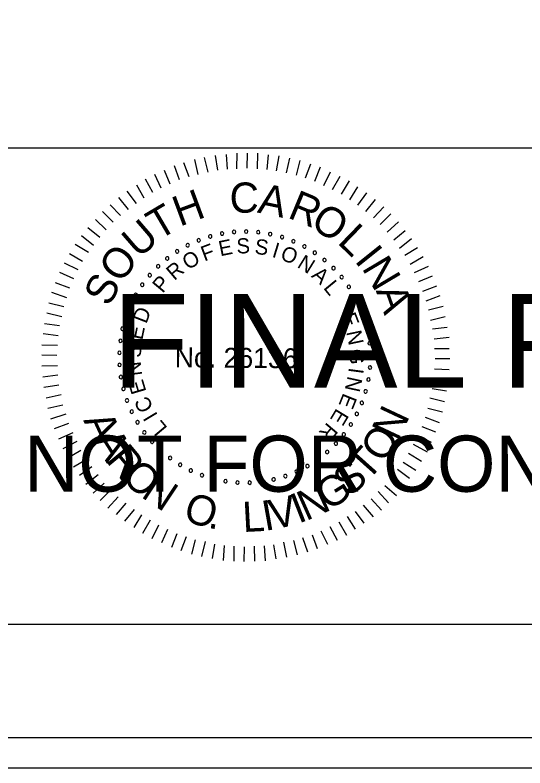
# Model space of a CAD drawing. Extents: x 967 to 1326, y 964 to 2304.
# Drawn here: x 1170.56 to 1189.3, y 1523.72 to 1551.36 of the extents above; entities that cross this region are included whole.
import ezdxf

# ---------------------------------------------------------------- set-up
doc = ezdxf.new("R2010")
doc.units = 0
for name, color, linetype in [('RD_PD_PaveShd', 7, 'Continuous'), ('RD_XS_Misc_Line', 7, 'Continuous'), ('RD_XS_PaveOvlay', 7, 'Continuous'), ('RD_XS_TX_Elev_EX', 7, 'Continuous'), ('RD_XS_TX_Elev_PR', 7, 'Continuous')]:
    doc.layers.add(name, color=color, linetype=linetype)

msp = doc.modelspace()

# ---------------------------------------------------------------- linework, layer by layer
at = {"layer": 'RD_PD_PaveShd'}
for p, q in [((996.114, 1546.486), (1323.886, 1546.486)), ((1323.886, 1528.983), (996.114, 1528.983))]:
    msp.add_line(p, q, dxfattribs=at)
at = {"layer": 'RD_XS_Misc_Line'}
for p, q in [((1178.01, 1545.663), (1177.93, 1546.209)), ((1178.364, 1545.699), (1178.33, 1546.244)), ((1178.717, 1545.719), (1178.722, 1546.295)), ((1179.093, 1545.739), (1179.098, 1546.292)), ((1179.469, 1545.713), (1179.489, 1546.288)), ((1179.829, 1545.687), (1179.872, 1546.231)), ((1180.174, 1545.646), (1180.271, 1546.19)), ((1176.964, 1545.419), (1176.769, 1545.935)), ((1177.287, 1545.508), (1177.169, 1546.054)), ((1177.657, 1545.597), (1177.53, 1546.128)), ((1180.535, 1545.573), (1180.662, 1546.102)), ((1180.902, 1545.478), (1181.045, 1546.022)), ((1181.231, 1545.384), (1181.428, 1545.896)), ((1176.264, 1545.156), (1176.053, 1545.657)), ((1176.61, 1545.306), (1176.423, 1545.83)), ((1181.584, 1545.265), (1181.78, 1545.786)), ((1175.933, 1545.005), (1175.699, 1545.506)), ((1181.905, 1545.109), (1182.154, 1545.606)), ((1182.226, 1544.953), (1182.506, 1545.45)), ((1175.308, 1544.634), (1175.036, 1545.12)), ((1175.624, 1544.846), (1175.352, 1545.332)), ((1182.562, 1544.789), (1182.85, 1545.27)), ((1175.03, 1544.445), (1174.681, 1544.9)), ((1182.86, 1544.572), (1183.163, 1545.053)), ((1183.158, 1544.378), (1183.484, 1544.828)), ((1174.729, 1544.217), (1174.372, 1544.665)), ((1183.447, 1544.145), (1183.811, 1544.587)), ((1174.435, 1543.997), (1174.062, 1544.399)), ((1183.729, 1543.92), (1184.116, 1544.316)), ((1174.172, 1543.753), (1173.776, 1544.148)), ((1183.98, 1543.672), (1184.368, 1544.061)), ((1173.909, 1543.479), (1173.52, 1543.858)), ((1184.232, 1543.394), (1184.657, 1543.767)), ((1173.684, 1543.197), (1173.242, 1543.546)), ((1184.475, 1543.108), (1184.892, 1543.45)), ((1173.451, 1542.9), (1173.009, 1543.256)), ((1184.687, 1542.807), (1185.128, 1543.156)), ((1173.257, 1542.64), (1172.776, 1542.936)), ((1173.039, 1542.312), (1172.559, 1542.6)), ((1184.885, 1542.544), (1185.355, 1542.832)), ((1185.081, 1542.213), (1185.56, 1542.493)), ((1172.883, 1542.006), (1172.379, 1542.256)), ((1185.24, 1541.904), (1185.756, 1542.145)), ((1172.727, 1541.677), (1172.215, 1541.904)), ((1185.399, 1541.573), (1185.907, 1541.791)), ((1172.571, 1541.333), (1172.051, 1541.53)), ((1185.549, 1541.226), (1186.057, 1541.414)), ((1172.461, 1540.974), (1171.91, 1541.178)), ((1185.669, 1540.865), (1186.185, 1541.06)), ((1172.351, 1540.652), (1171.807, 1540.787)), ((1185.759, 1540.541), (1186.297, 1540.667)), ((1172.286, 1540.276), (1171.727, 1540.419)), ((1185.832, 1540.165), (1186.371, 1540.298)), ((1172.191, 1539.955), (1171.647, 1540.029)), ((1185.906, 1539.842), (1186.436, 1539.906)), ((1172.15, 1539.587), (1171.598, 1539.653)), ((1185.964, 1539.473), (1186.51, 1539.53)), ((1172.124, 1539.234), (1171.548, 1539.239)), ((1185.977, 1539.12), (1186.514, 1539.115)), ((1172.105, 1538.866), (1171.545, 1538.871)), ((1185.997, 1538.751), (1186.542, 1538.747)), ((1172.118, 1538.482), (1171.542, 1538.471)), ((1185.971, 1538.368), (1186.508, 1538.348)), ((1172.138, 1538.136), (1171.585, 1538.072)), ((1185.952, 1538.022), (1186.497, 1537.949)), ((1172.173, 1537.768), (1171.627, 1537.688)), ((1185.888, 1537.655), (1186.417, 1537.566)), ((1172.262, 1537.414), (1171.701, 1537.296)), ((1185.808, 1537.302), (1186.345, 1537.175)), ((1172.321, 1537.037), (1171.774, 1536.911)), ((1185.729, 1536.926), (1186.265, 1536.792)), ((1172.425, 1536.707), (1171.871, 1536.519)), ((1185.634, 1536.597), (1186.146, 1536.401)), ((1172.53, 1536.36), (1172.007, 1536.173)), ((1185.508, 1536.253), (1186.013, 1536.057)), ((1172.681, 1536.029), (1172.165, 1535.788)), ((1172.831, 1535.705), (1172.323, 1535.441)), ((1185.352, 1535.924), (1185.857, 1535.675)), ((1185.188, 1535.603), (1185.7, 1535.33)), ((1172.982, 1535.374), (1172.497, 1535.094)), ((1185.024, 1535.274), (1185.498, 1534.987)), ((1173.194, 1535.042), (1172.709, 1534.762)), ((1184.822, 1534.946), (1185.288, 1534.658)), ((1173.384, 1534.78), (1172.936, 1534.453)), ((1184.62, 1534.687), (1185.055, 1534.353)), ((1173.612, 1534.478), (1173.164, 1534.129)), ((1184.403, 1534.389), (1184.814, 1534.033)), ((1173.832, 1534.177), (1173.437, 1533.812)), ((1184.155, 1534.092), (1184.574, 1533.72)), ((1174.091, 1533.945), (1173.689, 1533.541)), ((1183.899, 1533.864), (1184.28, 1533.454)), ((1174.35, 1533.674), (1173.97, 1533.263)), ((1183.644, 1533.597), (1184.024, 1533.18)), ((1174.64, 1533.442), (1174.275, 1533.022)), ((1174.937, 1533.209), (1174.58, 1532.782)), ((1183.358, 1533.37), (1183.715, 1532.944)), ((1175.212, 1533.014), (1174.932, 1532.549)), ((1182.764, 1532.952), (1183.059, 1532.482)), ((1183.065, 1533.141), (1183.384, 1532.709)), ((1175.525, 1532.812), (1175.245, 1532.331)), ((1175.83, 1532.633), (1175.588, 1532.136)), ((1182.463, 1532.755), (1182.743, 1532.269)), ((1176.159, 1532.477), (1175.94, 1531.98)), ((1181.8, 1532.431), (1182.041, 1531.93)), ((1182.124, 1532.581), (1182.396, 1532.08)), ((1176.503, 1532.321), (1176.307, 1531.816)), ((1176.855, 1532.211), (1176.651, 1531.69)), ((1177.177, 1532.1), (1177.05, 1531.572)), ((1181.122, 1532.175), (1181.31, 1531.652)), ((1181.476, 1532.28), (1181.664, 1531.771)), ((1177.545, 1532.036), (1177.409, 1531.484)), ((1177.897, 1531.933), (1177.808, 1531.412)), ((1178.25, 1531.892), (1178.207, 1531.34)), ((1178.603, 1531.866), (1178.598, 1531.313)), ((1178.978, 1531.84), (1178.974, 1531.295)), ((1179.355, 1531.86), (1179.365, 1531.307)), ((1179.715, 1531.88), (1179.749, 1531.327)), ((1180.061, 1531.915), (1180.149, 1531.393)), ((1180.423, 1532.012), (1180.541, 1531.458)), ((1180.791, 1532.07), (1180.926, 1531.54))]:
    msp.add_line(p, q, dxfattribs=at)
for centre, start, end in [((1178.609, 1543.397), 5.0653, 185.0653), ((1179.055, 1543.414), 359.5268, 179.5268), ((1179.055, 1543.414), 179.5268, 359.5268), ((1179.5, 1543.388), 353.9884, 173.9884), ((1177.312, 1543.091), 21.6807, 201.6807), ((1177.734, 1543.235), 16.1422, 196.1422), ((1177.734, 1543.235), 196.1422, 16.1422), ((1178.168, 1543.337), 10.6038, 190.6038), ((1178.168, 1543.337), 190.6038, 10.6038), ((1178.609, 1543.397), 185.0653, 5.0653), ((1179.5, 1543.388), 173.9884, 353.9884), ((1179.94, 1543.319), 168.4499, 348.4499), ((1179.94, 1543.319), 348.4499, 168.4499), ((1180.372, 1543.208), 162.9114, 342.9114), ((1180.372, 1543.208), 342.9114, 162.9114), ((1176.906, 1542.908), 27.2191, 207.2191), ((1176.906, 1542.908), 207.2191, 27.2191), ((1177.312, 1543.091), 201.6807, 21.6807), ((1180.79, 1543.056), 157.373, 337.373), ((1180.79, 1543.056), 337.373, 157.373), ((1181.193, 1542.864), 151.8345, 331.8345), ((1181.193, 1542.864), 331.8345, 151.8345), ((1176.52, 1542.686), 32.7576, 212.7576), ((1176.52, 1542.686), 212.7576, 32.7576), ((1181.574, 1542.634), 146.2961, 326.2961), ((1181.574, 1542.634), 326.2961, 146.2961), ((1176.156, 1542.428), 38.2961, 218.2961), ((1176.156, 1542.428), 218.2961, 38.2961), ((1181.932, 1542.368), 140.7576, 320.7576), ((1181.932, 1542.368), 320.7576, 140.7576), ((1175.82, 1542.135), 43.8345, 223.8345), ((1175.82, 1542.135), 223.8345, 43.8345), ((1182.263, 1542.069), 135.2191, 315.2191), ((1182.263, 1542.069), 315.2191, 135.2191), ((1175.513, 1541.812), 49.373, 229.373), ((1175.513, 1541.812), 229.373, 49.373), ((1182.563, 1541.74), 129.6807, 309.6807), ((1182.563, 1541.74), 309.6807, 129.6807), ((1175.239, 1541.461), 54.9114, 234.9114), ((1175.239, 1541.461), 234.9114, 54.9114), ((1182.83, 1541.383), 124.1422, 304.1422), ((1182.83, 1541.383), 304.1422, 124.1422), ((1175, 1541.085), 60.4499, 240.4499), ((1175, 1541.085), 240.4499, 60.4499), ((1183.061, 1541.002), 118.6038, 298.6038), ((1183.061, 1541.002), 298.6038, 118.6038), ((1174.798, 1540.687), 65.9884, 245.9884), ((1174.798, 1540.687), 245.9884, 65.9884), ((1183.255, 1540.601), 113.0653, 293.0653), ((1183.255, 1540.601), 293.0653, 113.0653), ((1174.636, 1540.272), 71.5268, 251.5268), ((1174.636, 1540.272), 251.5268, 71.5268), ((1183.408, 1540.182), 107.5268, 287.5268), ((1183.408, 1540.182), 287.5268, 107.5268), ((1174.514, 1539.843), 77.0653, 257.0653), ((1174.514, 1539.843), 257.0653, 77.0653), ((1183.521, 1539.751), 101.9884, 281.9884), ((1183.521, 1539.751), 281.9884, 101.9884), ((1174.435, 1539.405), 82.6038, 262.6038), ((1174.435, 1539.405), 262.6038, 82.6038), ((1183.592, 1539.311), 96.4499, 276.4499), ((1183.592, 1539.311), 276.4499, 96.4499), ((1174.398, 1538.961), 88.1422, 268.1422), ((1174.398, 1538.961), 268.1422, 88.1422), ((1183.619, 1538.866), 90.9114, 270.9114), ((1183.619, 1538.866), 270.9114, 90.9114), ((1174.404, 1538.515), 93.6807, 273.6807), ((1174.404, 1538.515), 273.6807, 93.6807), ((1183.604, 1538.421), 85.373, 265.373), ((1183.604, 1538.421), 265.373, 85.373), ((1174.453, 1538.072), 99.2191, 279.2191), ((1174.453, 1538.072), 279.2191, 99.2191), ((1183.546, 1537.979), 79.8345, 259.8345), ((1183.546, 1537.979), 259.8345, 79.8345), ((1174.545, 1537.636), 104.7576, 284.7576), ((1174.545, 1537.636), 284.7576, 104.7576), ((1183.445, 1537.545), 74.2961, 254.2961), ((1183.445, 1537.545), 254.2961, 74.2961), ((1174.678, 1537.211), 110.2961, 290.2961), ((1174.678, 1537.211), 290.2961, 110.2961), ((1183.303, 1537.122), 68.7576, 248.7576), ((1183.303, 1537.122), 248.7576, 68.7576), ((1174.852, 1536.8), 115.8345, 295.8345), ((1174.852, 1536.8), 295.8345, 115.8345), ((1183.121, 1536.716), 63.2191, 243.2191), ((1183.121, 1536.716), 243.2191, 63.2191), ((1175.065, 1536.409), 121.373, 301.373), ((1175.065, 1536.409), 301.373, 121.373), ((1182.9, 1536.328), 57.6807, 237.6807), ((1182.9, 1536.328), 237.6807, 57.6807), ((1175.314, 1536.039), 126.9114, 306.9114), ((1175.314, 1536.039), 306.9114, 126.9114), ((1182.643, 1535.964), 52.1422, 232.1422), ((1182.643, 1535.964), 232.1422, 52.1422), ((1175.598, 1535.696), 132.4499, 312.4499), ((1175.598, 1535.696), 312.4499, 132.4499), ((1182.353, 1535.627), 46.6038, 226.6038), ((1182.353, 1535.627), 226.6038, 46.6038), ((1175.914, 1535.381), 137.9884, 317.9884), ((1175.914, 1535.381), 317.9884, 137.9884), ((1176.258, 1535.099), 143.5268, 323.5268), ((1176.258, 1535.099), 323.5268, 143.5268), ((1182.03, 1535.319), 41.0653, 221.0653), ((1182.03, 1535.319), 221.0653, 41.0653), ((1176.629, 1534.851), 149.0653, 329.0653), ((1176.629, 1534.851), 329.0653, 149.0653), ((1181.305, 1534.803), 29.9884, 209.9884), ((1181.68, 1535.043), 35.5268, 215.5268), ((1181.68, 1535.043), 215.5268, 35.5268), ((1177.021, 1534.639), 154.6038, 334.6038), ((1177.021, 1534.639), 334.6038, 154.6038), ((1180.908, 1534.6), 24.4499, 204.4499), ((1180.908, 1534.6), 204.4499, 24.4499), ((1181.305, 1534.803), 209.9884, 29.9884), ((1177.432, 1534.467), 160.1422, 340.1422), ((1177.432, 1534.467), 340.1422, 160.1422), ((1177.858, 1534.335), 165.6807, 345.6807), ((1177.858, 1534.335), 345.6807, 165.6807), ((1178.294, 1534.245), 351.2191, 171.2191), ((1179.627, 1534.232), 7.8345, 187.8345), ((1180.065, 1534.313), 13.373, 193.373), ((1180.065, 1534.313), 193.373, 13.373), ((1180.494, 1534.436), 18.9114, 198.9114), ((1180.494, 1534.436), 198.9114, 18.9114), ((1178.294, 1534.245), 171.2191, 351.2191), ((1178.737, 1534.198), 356.7576, 176.7576), ((1178.737, 1534.198), 176.7576, 356.7576), ((1179.183, 1534.193), 2.2961, 182.2961), ((1179.183, 1534.193), 182.2961, 2.2961), ((1179.627, 1534.232), 187.8345, 7.8345)]:
    msp.add_arc(centre, 0.0627, start, end, dxfattribs=at)
at = {"layer": 'RD_XS_PaveOvlay'}
msp.add_lwpolyline([(967.409, 1523.72), (1326.285, 1523.72), (1326.285, 1743.72), (967.409, 1743.72)], close=True, dxfattribs=at)
at = {"layer": 'RD_XS_TX_Elev_EX'}
for points in [[(967.409, 1523.72), (1326.285, 1523.72), (1326.285, 1743.72), (967.409, 1743.72)], [(988.525, 1524.84), (1326.285, 1524.84), (1326.285, 1742.6), (988.525, 1742.6)]]:
    msp.add_lwpolyline(points, close=True, dxfattribs=at)

# ---------------------------------------------------------------- texts
at = {"layer": 'RD_XS_Misc_Line'}
for s, height, rotation, p in [('C', 1.11, 359.5482, (1178.442, 1544.108)), ('A', 1.11, 348.1981, (1179.439, 1544.115)), ('H', 1.11, 20.3637, (1176.614, 1543.587)), ('R', 1.11, 337.4344, (1180.541, 1543.937)), ('T', 1.11, 30.4992, (1175.828, 1543.072)), ('O', 1.108, 326.5869, (1181.366, 1543.609)), ('U', 1.11, 40.8022, (1175.102, 1542.403)), ('L', 1.11, 315.9488, (1182.373, 1543.003)), ('E', 0.557, 11.4103, (1178.103, 1542.503)), ('S', 0.557, 2.208, (1178.709, 1542.601)), ('S', 0.557, 352.6608, (1179.346, 1542.599)), ('F', 0.557, 20.6127, (1177.52, 1542.309)), ('I', 0.557, 343.1136, (1179.975, 1542.491)), ('O', 0.557, 338.4392, (1180.274, 1542.401)), ('I', 1.11, 308.6613, (1183.011, 1542.338)), ('O', 1.11, 52.0267, (1174.435, 1541.474)), ('O', 0.557, 30.8477, (1176.917, 1541.987)), ('N', 0.557, 328.2042, (1180.896, 1542.12)), ('N', 1.11, 300.7037, (1183.285, 1542.075)), ('R', 0.557, 40.3949, (1176.415, 1541.594)), ('A', 0.557, 318.657, (1181.424, 1541.762)), ('S', 1.108, 63.2511, (1174.029, 1540.619)), ('P', 0.557, 49.9421, (1175.985, 1541.124)), ('L', 0.557, 309.4546, (1181.869, 1541.339)), ('A', 1.11, 289.4792, (1183.814, 1541.243)), ('D', 0.557, 69.0364, (1175.386, 1540.003)), ('E', 0.557, 291.049, (1182.53, 1540.307)), ('E', 0.557, 78.2388, (1175.238, 1539.407)), ('N', 0.557, 281.8466, (1182.728, 1539.726)), ('S', 0.557, 87.786, (1175.187, 1538.772)), ('No. 26136', 0.7311, 359.5268, (1176.429, 1538.43)), ('G', 0.557, 272.2995, (1182.833, 1539.097)), ('N', 0.557, 97.3332, (1175.242, 1538.137)), ('I', 0.557, 262.4084, (1182.83, 1538.437)), ('E', 0.557, 106.5355, (1175.394, 1537.541)), ('N', 0.557, 257.7339, (1182.789, 1538.127)), ('C', 0.557, 116.4266, (1175.661, 1536.938)), ('E', 0.557, 248.1867, (1182.628, 1537.511)), ('I', 0.557, 121.1011, (1175.823, 1536.67)), ('E', 0.557, 238.9844, (1182.378, 1536.949)), ('N', 1.105, 64.8922, (1184.632, 1535.684)), ('A', 1.105, 294.7297, (1173.062, 1536.486)), ('L', 0.557, 129.9595, (1176.187, 1536.204)), ('R', 0.557, 229.782, (1182.041, 1536.435)), ('O', 1.105, 56.2059, (1184.102, 1534.874)), ('A', 1.105, 302.2892, (1173.414, 1535.72)), ('R', 1.105, 309.8487, (1173.865, 1535.007)), ('T', 1.105, 48.2685, (1183.515, 1534.211)), ('O', 1.105, 317.7861, (1174.434, 1534.33)), ('S', 1.105, 40.3311, (1182.842, 1533.636)), ('N', 1.105, 326.4725, (1175.158, 1533.686)), ('G', 1.105, 32.0198, (1182.059, 1533.14)), ('N', 1.105, 24.0824, (1181.252, 1532.776)), ('O', 1.105, 342.3472, (1176.697, 1532.82)), ('V', 1.105, 12.7741, (1180.033, 1532.457)), ('I', 1.105, 21.4605, (1180.976, 1532.681)), ('L', 1.105, 2.9677, (1178.943, 1532.379)), ('I', 1.105, 10.1523, (1179.743, 1532.418)), ('.', 1.105, 351.0336, (1177.623, 1532.536))]:
    msp.add_text(s, height=height, rotation=rotation, dxfattribs=at).set_placement(p)
at = {"layer": 'RD_XS_TX_Elev_PR'}
for s, height, p in [('FINAL PLANS', 3.4375, (1174.145, 1537.685)), ('NOT FOR CONSTRUCTION', 2.0625, (1170.901, 1533.86))]:
    msp.add_text(s, height=height, dxfattribs=at).set_placement(p)

doc.saveas('drawing.dxf')
